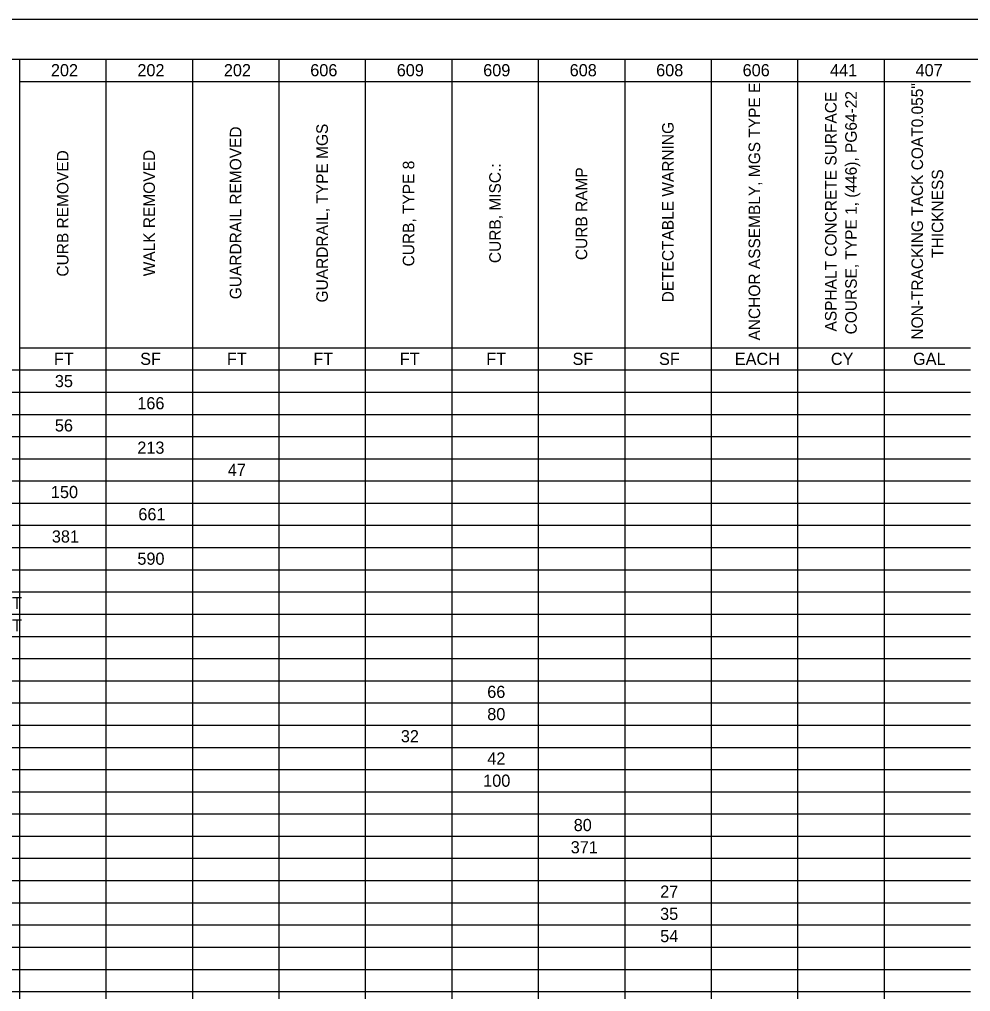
# Model space of a CAD drawing. Extents: x 0 to 34, y 0 to 22.
# Drawn here: x 8.32 to 20.31, y 9.75 to 22 of the extents above; entities that cross this region are included whole.
import ezdxf

# ---------------------------------------------------------------- set-up
doc = ezdxf.new("R2010")
doc.units = 0
for name, color, linetype in [('Default', 7, 'Continuous'), ('SH_Border', 7, 'Continuous'), ('SH_Cut_Line', 7, 'Continuous')]:
    doc.layers.add(name, color=color, linetype=linetype)

msp = doc.modelspace()

# ---------------------------------------------------------------- linework, layer by layer
at = {"layer": 'Default'}
for p, q in [((5.631, 21.5), (8.318, 21.5)), ((8.318, 21.5), (12.678, 21.5)), ((8.318, 21.5), (8.318, 21.22)), ((9.408, 21.5), (9.408, 21.22)), ((10.498, 21.5), (10.498, 21.22)), ((11.588, 21.5), (11.588, 21.22)), ((12.678, 21.5), (15.948, 21.5)), ((12.678, 21.5), (12.678, 21.22)), ((13.768, 21.5), (13.768, 21.22)), ((14.858, 21.5), (14.858, 21.22)), ((15.948, 21.5), (20.307, 21.5)), ((15.948, 21.5), (15.948, 21.22)), ((17.037, 21.5), (17.037, 21.22)), ((18.127, 21.5), (18.127, 21.22)), ((19.217, 21.5), (19.217, 21.22)), ((8.318, 21.22), (12.678, 21.22)), ((8.318, 21.22), (8.318, 20.941)), ((9.408, 21.22), (9.408, 20.941)), ((10.498, 21.22), (10.498, 20.941)), ((11.588, 21.22), (11.588, 20.941)), ((12.678, 21.22), (15.948, 21.22)), ((12.678, 21.22), (12.678, 20.941)), ((13.768, 21.22), (13.768, 20.941)), ((14.858, 21.22), (14.858, 20.941)), ((15.948, 21.22), (20.307, 21.22)), ((15.948, 21.22), (15.948, 20.941)), ((17.037, 21.22), (17.037, 20.941)), ((18.127, 21.22), (18.127, 20.941)), ((19.217, 21.22), (19.217, 20.941)), ((8.318, 20.941), (8.318, 20.661)), ((9.408, 20.941), (9.408, 20.661)), ((10.498, 20.941), (10.498, 20.661)), ((11.588, 20.941), (11.588, 20.661)), ((12.678, 20.941), (12.678, 20.661)), ((13.768, 20.941), (13.768, 20.661)), ((14.858, 20.941), (14.858, 20.661)), ((15.948, 20.941), (15.948, 20.661)), ((17.037, 20.941), (17.037, 20.661)), ((18.127, 20.941), (18.127, 20.661)), ((19.217, 20.941), (19.217, 20.661)), ((8.318, 20.661), (8.318, 20.381)), ((9.408, 20.661), (9.408, 20.381)), ((10.498, 20.661), (10.498, 20.381)), ((11.588, 20.661), (11.588, 20.381)), ((12.678, 20.661), (12.678, 20.381)), ((13.768, 20.661), (13.768, 20.381)), ((14.858, 20.661), (14.858, 20.381)), ((15.948, 20.661), (15.948, 20.381)), ((17.037, 20.661), (17.037, 20.381)), ((18.127, 20.661), (18.127, 20.381)), ((19.217, 20.661), (19.217, 20.381)), ((8.318, 20.381), (8.318, 20.101)), ((9.408, 20.381), (9.408, 20.101)), ((10.498, 20.381), (10.498, 20.101)), ((11.588, 20.381), (11.588, 20.101)), ((12.678, 20.381), (12.678, 20.101)), ((13.768, 20.381), (13.768, 20.101)), ((14.858, 20.381), (14.858, 20.101)), ((15.948, 20.381), (15.948, 20.101)), ((17.037, 20.381), (17.037, 20.101)), ((18.127, 20.381), (18.127, 20.101)), ((19.217, 20.381), (19.217, 20.101)), ((8.318, 20.101), (8.318, 19.822)), ((9.408, 20.101), (9.408, 19.822)), ((10.498, 20.101), (10.498, 19.822)), ((11.588, 20.101), (11.588, 19.822)), ((12.678, 20.101), (12.678, 19.822)), ((13.768, 20.101), (13.768, 19.822)), ((14.858, 20.101), (14.858, 19.822)), ((15.948, 20.101), (15.948, 19.822)), ((17.037, 20.101), (17.037, 19.822)), ((18.127, 20.101), (18.127, 19.822)), ((19.217, 20.101), (19.217, 19.822)), ((8.318, 19.822), (8.318, 19.542)), ((9.408, 19.822), (9.408, 19.542)), ((10.498, 19.822), (10.498, 19.542)), ((11.588, 19.822), (11.588, 19.542)), ((12.678, 19.822), (12.678, 19.542)), ((13.768, 19.822), (13.768, 19.542)), ((14.858, 19.822), (14.858, 19.542)), ((15.948, 19.822), (15.948, 19.542)), ((17.037, 19.822), (17.037, 19.542)), ((18.127, 19.822), (18.127, 19.542)), ((19.217, 19.822), (19.217, 19.542)), ((8.318, 19.542), (8.318, 18.982)), ((9.408, 19.542), (9.408, 18.982)), ((10.498, 19.542), (10.498, 18.982)), ((11.588, 19.542), (11.588, 18.982)), ((12.678, 19.542), (12.678, 18.982)), ((13.768, 19.542), (13.768, 18.982)), ((14.858, 19.542), (14.858, 18.982)), ((15.948, 19.542), (15.948, 18.982)), ((17.037, 19.542), (17.037, 18.982)), ((18.127, 19.542), (18.127, 18.982)), ((19.217, 19.542), (19.217, 18.982)), ((8.318, 18.982), (8.318, 18.143)), ((9.408, 18.982), (9.408, 18.143)), ((10.498, 18.982), (10.498, 18.143)), ((11.588, 18.982), (11.588, 18.143)), ((12.678, 18.982), (12.678, 18.143)), ((13.768, 18.982), (13.768, 18.143)), ((14.858, 18.982), (14.858, 18.143)), ((15.948, 18.982), (15.948, 18.143)), ((17.037, 18.982), (17.037, 18.143)), ((18.127, 18.982), (18.127, 18.143)), ((19.217, 18.982), (19.217, 18.143)), ((8.318, 18.143), (8.318, 17.864)), ((9.408, 18.143), (9.408, 17.864)), ((10.498, 18.143), (10.498, 17.864)), ((11.588, 18.143), (11.588, 17.864)), ((12.678, 18.143), (12.678, 17.864)), ((13.768, 18.143), (13.768, 17.864)), ((14.858, 18.143), (14.858, 17.864)), ((15.948, 18.143), (15.948, 17.864)), ((17.037, 18.143), (17.037, 17.864)), ((18.127, 18.143), (18.127, 17.864)), ((19.217, 18.143), (19.217, 17.864)), ((8.318, 17.864), (12.678, 17.864)), ((8.318, 17.864), (8.318, 17.304)), ((9.408, 17.864), (9.408, 17.304)), ((10.498, 17.864), (10.498, 17.304)), ((11.588, 17.864), (11.588, 17.304)), ((12.678, 17.864), (15.948, 17.864)), ((12.678, 17.864), (12.678, 17.304)), ((13.768, 17.864), (13.768, 17.304)), ((14.858, 17.864), (14.858, 17.304)), ((15.948, 17.864), (20.307, 17.864)), ((15.948, 17.864), (15.948, 17.304)), ((17.037, 17.864), (17.037, 17.304)), ((18.127, 17.864), (18.127, 17.304)), ((19.217, 17.864), (19.217, 17.304)), ((5.631, 17.584), (8.318, 17.584)), ((8.318, 17.584), (12.678, 17.584)), ((12.678, 17.584), (15.948, 17.584)), ((15.948, 17.584), (20.307, 17.584)), ((5.631, 17.304), (8.318, 17.304)), ((8.318, 17.304), (12.678, 17.304)), ((8.318, 17.304), (8.318, 17.024)), ((9.408, 17.304), (9.408, 17.024)), ((10.498, 17.304), (10.498, 17.024)), ((11.588, 17.304), (11.588, 17.024)), ((12.678, 17.304), (15.948, 17.304)), ((12.678, 17.304), (12.678, 17.024)), ((13.768, 17.304), (13.768, 17.024)), ((14.858, 17.304), (14.858, 17.024)), ((15.948, 17.304), (20.307, 17.304)), ((15.948, 17.304), (15.948, 17.024)), ((17.037, 17.304), (17.037, 17.024)), ((18.127, 17.304), (18.127, 17.024)), ((19.217, 17.304), (19.217, 17.024)), ((5.631, 17.024), (8.318, 17.024)), ((8.318, 17.024), (12.678, 17.024)), ((8.318, 17.024), (8.318, 15.905)), ((9.408, 17.024), (9.408, 15.905)), ((10.498, 17.024), (10.498, 15.905)), ((11.588, 17.024), (11.588, 15.905)), ((12.678, 17.024), (15.948, 17.024)), ((12.678, 17.024), (12.678, 15.905)), ((13.768, 17.024), (13.768, 15.905)), ((14.858, 17.024), (14.858, 15.905)), ((15.948, 17.024), (20.307, 17.024)), ((15.948, 17.024), (15.948, 15.905)), ((17.037, 17.024), (17.037, 15.905)), ((18.127, 17.024), (18.127, 15.905)), ((19.217, 17.024), (19.217, 15.905)), ((5.631, 16.745), (8.318, 16.745)), ((8.318, 16.745), (12.678, 16.745)), ((12.678, 16.745), (15.948, 16.745)), ((15.948, 16.745), (20.307, 16.745)), ((5.631, 16.465), (8.318, 16.465)), ((8.318, 16.465), (12.678, 16.465)), ((12.678, 16.465), (15.948, 16.465)), ((15.948, 16.465), (20.307, 16.465)), ((5.631, 16.185), (8.318, 16.185)), ((8.318, 16.185), (12.678, 16.185)), ((12.678, 16.185), (15.948, 16.185)), ((15.948, 16.185), (20.307, 16.185)), ((5.631, 15.905), (8.318, 15.905)), ((8.318, 15.905), (12.678, 15.905)), ((8.318, 15.905), (8.318, 15.626)), ((9.408, 15.905), (9.408, 15.626)), ((10.498, 15.905), (10.498, 15.626)), ((11.588, 15.905), (11.588, 15.626)), ((12.678, 15.905), (15.948, 15.905)), ((12.678, 15.905), (12.678, 15.626)), ((13.768, 15.905), (13.768, 15.626)), ((14.858, 15.905), (14.858, 15.626)), ((15.948, 15.905), (20.307, 15.905)), ((15.948, 15.905), (15.948, 15.626)), ((17.037, 15.905), (17.037, 15.626)), ((18.127, 15.905), (18.127, 15.626)), ((19.217, 15.905), (19.217, 15.626)), ((5.631, 15.626), (8.318, 15.626)), ((8.318, 15.626), (12.678, 15.626)), ((8.318, 15.626), (8.318, 15.066)), ((9.408, 15.626), (9.408, 15.066)), ((10.498, 15.626), (10.498, 15.066)), ((11.588, 15.626), (11.588, 15.066)), ((12.678, 15.626), (15.948, 15.626)), ((12.678, 15.626), (12.678, 15.066)), ((13.768, 15.626), (13.768, 15.066)), ((14.858, 15.626), (14.858, 15.066)), ((15.948, 15.626), (20.307, 15.626)), ((15.948, 15.626), (15.948, 15.066)), ((17.037, 15.626), (17.037, 15.066)), ((18.127, 15.626), (18.127, 15.066)), ((19.217, 15.626), (19.217, 15.066)), ((5.631, 15.346), (8.318, 15.346)), ((8.318, 15.346), (12.678, 15.346)), ((12.678, 15.346), (15.948, 15.346)), ((15.948, 15.346), (20.307, 15.346)), ((5.631, 15.066), (8.318, 15.066)), ((8.318, 15.066), (12.678, 15.066)), ((8.318, 15.066), (8.318, 14.507)), ((9.408, 15.066), (9.408, 14.507)), ((10.498, 15.066), (10.498, 14.507)), ((11.588, 15.066), (11.588, 14.507)), ((12.678, 15.066), (15.948, 15.066)), ((12.678, 15.066), (12.678, 14.507)), ((13.768, 15.066), (13.768, 14.507)), ((14.858, 15.066), (14.858, 14.507)), ((15.948, 15.066), (20.307, 15.066)), ((15.948, 15.066), (15.948, 14.507)), ((17.037, 15.066), (17.037, 14.507)), ((18.127, 15.066), (18.127, 14.507)), ((19.217, 15.066), (19.217, 14.507)), ((5.631, 14.786), (8.318, 14.786)), ((8.318, 14.786), (12.678, 14.786)), ((12.678, 14.786), (15.948, 14.786)), ((15.948, 14.786), (20.307, 14.786)), ((5.631, 14.507), (8.318, 14.507)), ((8.318, 14.507), (12.678, 14.507)), ((8.318, 14.507), (8.318, 14.227)), ((9.408, 14.507), (9.408, 14.227)), ((10.498, 14.507), (10.498, 14.227)), ((11.588, 14.507), (11.588, 14.227)), ((12.678, 14.507), (15.948, 14.507)), ((12.678, 14.507), (12.678, 14.227)), ((13.768, 14.507), (13.768, 14.227)), ((14.858, 14.507), (14.858, 14.227)), ((15.948, 14.507), (20.307, 14.507)), ((15.948, 14.507), (15.948, 14.227)), ((17.037, 14.507), (17.037, 14.227)), ((18.127, 14.507), (18.127, 14.227)), ((19.217, 14.507), (19.217, 14.227)), ((5.631, 14.227), (8.318, 14.227)), ((8.318, 14.227), (12.678, 14.227)), ((8.318, 14.227), (8.318, 13.668)), ((9.408, 14.227), (9.408, 13.668)), ((10.498, 14.227), (10.498, 13.668)), ((11.588, 14.227), (11.588, 13.668)), ((12.678, 14.227), (15.948, 14.227)), ((12.678, 14.227), (12.678, 13.668)), ((13.768, 14.227), (13.768, 13.668)), ((14.858, 14.227), (14.858, 13.668)), ((15.948, 14.227), (20.307, 14.227)), ((15.948, 14.227), (15.948, 13.668)), ((17.037, 14.227), (17.037, 13.668)), ((18.127, 14.227), (18.127, 13.668)), ((19.217, 14.227), (19.217, 13.668)), ((5.631, 13.947), (8.318, 13.947)), ((8.318, 13.947), (12.678, 13.947)), ((12.678, 13.947), (15.948, 13.947)), ((15.948, 13.947), (20.307, 13.947)), ((5.631, 13.668), (8.318, 13.668)), ((8.318, 13.668), (12.678, 13.668)), ((8.318, 13.668), (8.318, 13.388)), ((9.408, 13.668), (9.408, 13.388)), ((10.498, 13.668), (10.498, 13.388)), ((11.588, 13.668), (11.588, 13.388)), ((12.678, 13.668), (15.948, 13.668)), ((12.678, 13.668), (12.678, 13.388)), ((13.768, 13.668), (13.768, 13.388)), ((14.858, 13.668), (14.858, 13.388)), ((15.948, 13.668), (20.307, 13.668)), ((15.948, 13.668), (15.948, 13.388)), ((17.037, 13.668), (17.037, 13.388)), ((18.127, 13.668), (18.127, 13.388)), ((19.217, 13.668), (19.217, 13.388)), ((5.631, 13.388), (8.318, 13.388)), ((8.318, 13.388), (12.678, 13.388)), ((8.318, 13.388), (8.318, 12.549)), ((9.408, 13.388), (9.408, 12.549)), ((10.498, 13.388), (10.498, 12.549)), ((11.588, 13.388), (11.588, 12.549)), ((12.678, 13.388), (15.948, 13.388)), ((12.678, 13.388), (12.678, 12.549)), ((13.768, 13.388), (13.768, 12.549)), ((14.858, 13.388), (14.858, 12.549)), ((15.948, 13.388), (20.307, 13.388)), ((15.948, 13.388), (15.948, 12.549)), ((17.037, 13.388), (17.037, 12.549)), ((18.127, 13.388), (18.127, 12.549)), ((19.217, 13.388), (19.217, 12.549)), ((5.631, 13.108), (8.318, 13.108)), ((8.318, 13.108), (12.678, 13.108)), ((12.678, 13.108), (15.948, 13.108)), ((15.948, 13.108), (20.307, 13.108)), ((5.631, 12.828), (8.318, 12.828)), ((8.318, 12.828), (12.678, 12.828)), ((12.678, 12.828), (15.948, 12.828)), ((15.948, 12.828), (20.307, 12.828)), ((5.631, 12.549), (8.318, 12.549)), ((8.318, 12.549), (12.678, 12.549)), ((8.318, 12.549), (8.318, 11.989)), ((9.408, 12.549), (9.408, 11.989)), ((10.498, 12.549), (10.498, 11.989)), ((11.588, 12.549), (11.588, 11.989)), ((12.678, 12.549), (15.948, 12.549)), ((12.678, 12.549), (12.678, 11.989)), ((13.768, 12.549), (13.768, 11.989)), ((14.858, 12.549), (14.858, 11.989)), ((15.948, 12.549), (20.307, 12.549)), ((15.948, 12.549), (15.948, 11.989)), ((17.037, 12.549), (17.037, 11.989)), ((18.127, 12.549), (18.127, 11.989)), ((19.217, 12.549), (19.217, 11.989)), ((5.631, 12.269), (8.318, 12.269)), ((8.318, 12.269), (12.678, 12.269)), ((12.678, 12.269), (15.948, 12.269)), ((15.948, 12.269), (20.307, 12.269)), ((5.631, 11.989), (8.318, 11.989)), ((8.318, 11.989), (12.678, 11.989)), ((8.318, 11.989), (8.318, 11.15)), ((9.408, 11.989), (9.408, 11.15)), ((10.498, 11.989), (10.498, 11.15)), ((11.588, 11.989), (11.588, 11.15)), ((12.678, 11.989), (15.948, 11.989)), ((12.678, 11.989), (12.678, 11.15)), ((13.768, 11.989), (13.768, 11.15)), ((14.858, 11.989), (14.858, 11.15)), ((15.948, 11.989), (20.307, 11.989)), ((15.948, 11.989), (15.948, 11.15)), ((17.037, 11.989), (17.037, 11.15)), ((18.127, 11.989), (18.127, 11.15)), ((19.217, 11.989), (19.217, 11.15)), ((5.631, 11.709), (8.318, 11.709)), ((8.318, 11.709), (12.678, 11.709)), ((12.678, 11.709), (15.948, 11.709)), ((15.948, 11.709), (20.307, 11.709)), ((5.631, 11.43), (8.318, 11.43)), ((8.318, 11.43), (12.678, 11.43)), ((12.678, 11.43), (15.948, 11.43)), ((15.948, 11.43), (20.307, 11.43)), ((5.631, 11.15), (8.318, 11.15)), ((8.318, 11.15), (12.678, 11.15)), ((8.318, 11.15), (8.318, 10.591)), ((9.408, 11.15), (9.408, 10.591)), ((10.498, 11.15), (10.498, 10.591)), ((11.588, 11.15), (11.588, 10.591)), ((12.678, 11.15), (15.948, 11.15)), ((12.678, 11.15), (12.678, 10.591)), ((13.768, 11.15), (13.768, 10.591)), ((14.858, 11.15), (14.858, 10.591)), ((15.948, 11.15), (20.307, 11.15)), ((15.948, 11.15), (15.948, 10.591)), ((17.037, 11.15), (17.037, 10.591)), ((18.127, 11.15), (18.127, 10.591)), ((19.217, 11.15), (19.217, 10.591)), ((5.631, 10.87), (8.318, 10.87)), ((8.318, 10.87), (12.678, 10.87)), ((12.678, 10.87), (15.948, 10.87)), ((15.948, 10.87), (20.307, 10.87)), ((5.631, 10.591), (8.318, 10.591)), ((8.318, 10.591), (12.678, 10.591)), ((8.318, 10.591), (8.318, 9.751)), ((9.408, 10.591), (9.408, 9.751)), ((10.498, 10.591), (10.498, 9.751)), ((11.588, 10.591), (11.588, 9.751)), ((12.678, 10.591), (15.948, 10.591)), ((12.678, 10.591), (12.678, 9.751)), ((13.768, 10.591), (13.768, 9.751)), ((14.858, 10.591), (14.858, 9.751)), ((15.948, 10.591), (20.307, 10.591)), ((15.948, 10.591), (15.948, 9.751)), ((17.037, 10.591), (17.037, 9.751)), ((18.127, 10.591), (18.127, 9.751)), ((19.217, 10.591), (19.217, 9.751)), ((5.631, 10.311), (8.318, 10.311)), ((8.318, 10.311), (12.678, 10.311)), ((12.678, 10.311), (15.948, 10.311)), ((15.948, 10.311), (20.307, 10.311)), ((5.631, 10.031), (8.318, 10.031)), ((8.318, 10.031), (12.678, 10.031)), ((12.678, 10.031), (15.948, 10.031)), ((15.948, 10.031), (20.307, 10.031)), ((5.631, 9.751), (8.318, 9.751)), ((8.318, 9.751), (12.678, 9.751)), ((8.318, 9.751), (8.318, 9.192)), ((9.408, 9.751), (9.408, 9.192)), ((10.498, 9.751), (10.498, 9.192)), ((11.588, 9.751), (11.588, 9.192)), ((12.678, 9.751), (15.948, 9.751)), ((12.678, 9.751), (12.678, 9.192)), ((13.768, 9.751), (13.768, 9.192)), ((14.858, 9.751), (14.858, 9.192)), ((15.948, 9.751), (20.307, 9.751)), ((15.948, 9.751), (15.948, 9.192)), ((17.037, 9.751), (17.037, 9.192)), ((18.127, 9.751), (18.127, 9.192)), ((19.217, 9.751), (19.217, 9.192))]:
    msp.add_line(p, q, dxfattribs=at)
at = {"layer": 'SH_Border'}
msp.add_lwpolyline([(1.5, 21.5), (33.5, 21.5), (33.5, 0.5), (1.5, 0.5)], close=True, dxfattribs=at)
at = {"layer": 'SH_Cut_Line'}
msp.add_lwpolyline([(0, 0), (34, 0), (34, 22), (0, 22)], close=True, dxfattribs=at)

# ---------------------------------------------------------------- texts
at = {"layer": 'Default'}
for s, p in [('202', (8.715, 21.284)), ('202', (9.805, 21.284)), ('202', (10.895, 21.284)), ('606', (11.984, 21.284)), ('609', (13.074, 21.284)), ('609', (14.164, 21.284)), ('608', (15.254, 21.284)), ('608', (16.344, 21.284)), ('606', (17.434, 21.284)), ('441', (18.536, 21.284)), ('407', (19.614, 21.284)), ('FT', (8.753, 17.647)), ('SF', (9.84, 17.647)), ('FT', (10.933, 17.647)), ('FT', (12.023, 17.647)), ('FT', (13.113, 17.647)), ('FT', (14.203, 17.647)), ('SF', (15.29, 17.647)), ('SF', (16.38, 17.647)), ('EACH', (17.335, 17.647)), ('CY', (18.546, 17.647)), ('GAL', (19.582, 17.647)), ('35', (8.765, 17.367)), ('166', (9.804, 17.088)), ('56', (8.765, 16.808)), ('213', (9.804, 16.528)), ('47', (10.945, 16.248)), ('150', (8.715, 15.969)), ('661', (9.817, 15.689)), ('381', (8.727, 15.409)), ('590', (9.805, 15.129)), ('24.7 RT', (7.622, 14.57)), ('62.1 RT', (7.622, 14.29)), ('66', (14.215, 13.451)), ('80', (14.215, 13.171)), ('32', (13.126, 12.892)), ('42', (14.216, 12.612)), ('100', (14.164, 12.332)), ('80', (15.305, 11.773)), ('371', (15.267, 11.493)), ('27', (16.395, 10.934)), ('35', (16.394, 10.654)), ('54', (16.395, 10.374))]:
    msp.add_text(s, height=0.1532, dxfattribs=at).set_placement(p)
for s, height, p in [('ANCHOR ASSEMBLY, MGS TYPE E', 0.14574, (17.655, 17.955)), ('ASPHALT CONCRETE SURFACE ', 0.14574, (18.618, 18.068)), ('COURSE, TYPE 1, (446), PG64-22', 0.14574, (18.873, 18.032)), ('NON-TRACKING TACK COAT0.055" ', 0.14574, (19.708, 17.966)), ('GUARDRAIL REMOVED', 0.14574, (11.116, 18.475)), ('GUARDRAIL, TYPE MGS', 0.14574, (12.206, 18.434)), ('DETECTABLE WARNING', 0.14574, (16.565, 18.435)), ('CURB REMOVED', 0.14574, (8.936, 18.76)), ('WALK REMOVED', 0.14574, (10.026, 18.764)), ('CURB, TYPE 8', 0.14574, (13.296, 18.888)), ('CURB, MISC.:', 0.14574, (14.386, 18.93)), ('CURB RAMP', 0.1457, (15.475, 18.968)), ('THICKNESS', 0.1457, (19.963, 18.996))]:
    msp.add_text(s, height=height, rotation=90, dxfattribs=at).set_placement(p)

doc.saveas('drawing.dxf')
